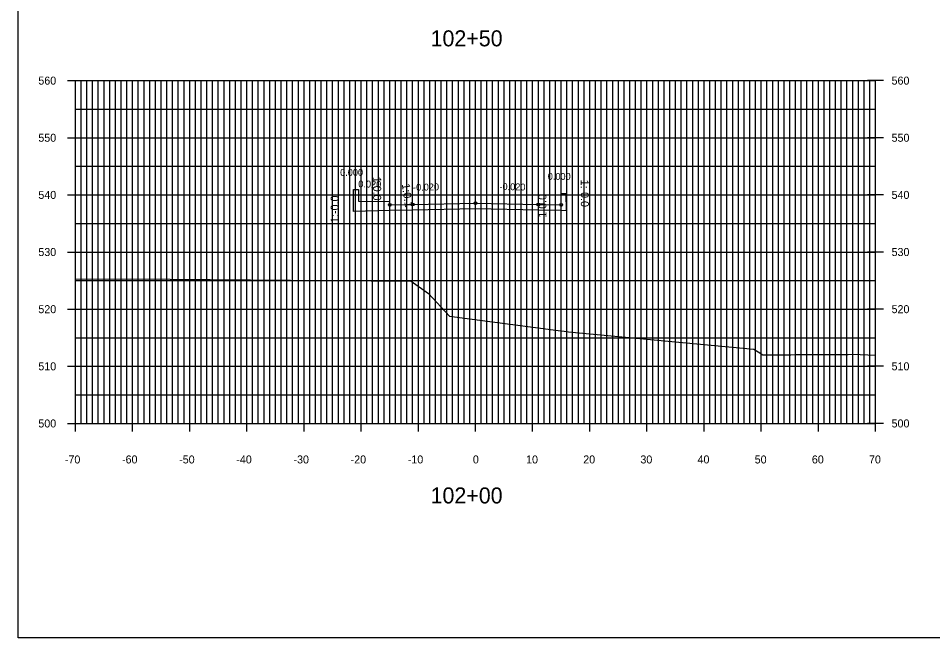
# Model space of a CAD drawing. Extents: x 1509063 to 1512863, y 401160 to 402918.
# Drawn here: x 1511462.7 to 1511622.7, y 402252.1 to 402360.5 of the extents above; entities that cross this region are included whole.
import ezdxf

# ---------------------------------------------------------------- set-up
doc = ezdxf.new("R2010")
doc.units = 0
for name, color, linetype in [('NBL1', 7, 'Continuous'), ('PET_P', 7, 'Continuous'), ('PRC', 7, 'Continuous'), ('PSP_P', 7, 'Continuous'), ('XAX_P', 7, 'Continuous'), ('XAXTIC_P', 7, 'Continuous'), ('XAXTXT_P_T', 7, 'Continuous'), ('XGL_P', 7, 'Continuous'), ('XSL1_P', 7, 'Continuous'), ('XSL1_P_T', 7, 'Continuous'), ('XSL3_P', 7, 'Continuous'), ('XSLOG', 7, 'Continuous')]:
    doc.layers.add(name, color=color, linetype=linetype)

msp = doc.modelspace()

# ---------------------------------------------------------------- linework, layer by layer
at = {"layer": 'NBL1'}
msp.add_lwpolyline([(1511782.73, 402252.08), (1511462.73, 402252.08), (1511462.73, 402462.08), (1511782.73, 402462.08)], close=True, dxfattribs=at)
at = {"layer": 'PET_P'}
for centre in [(1511531.73, 402327.9), (1511553.73, 402327.9)]:
    msp.add_circle(centre, 0.25, dxfattribs=at)
at = {"layer": 'PRC'}
msp.add_circle((1511542.73, 402328.12), 0.25, dxfattribs=at)
at = {"layer": 'PSP_P'}
for centre in [(1511527.73, 402327.82), (1511557.73, 402327.82)]:
    msp.add_circle(centre, 0.25, dxfattribs=at)
at = {"layer": 'XAX_P'}
for p, q in [((1511472.73, 402289.58), (1511472.73, 402349.58)), ((1511542.73, 402289.58), (1511542.73, 402349.58)), ((1511612.73, 402289.58), (1511612.73, 402349.58)), ((1511472.73, 402289.58), (1511612.73, 402289.58))]:
    msp.add_line(p, q, dxfattribs=at)
at = {"layer": 'XAXTIC_P'}
for p, q in [((1511471.33, 402349.58), (1511474.13, 402349.58)), ((1511541.33, 402349.58), (1511544.13, 402349.58)), ((1511614.13, 402349.58), (1511611.33, 402349.58)), ((1511471.33, 402339.58), (1511474.13, 402339.58)), ((1511541.33, 402339.58), (1511544.13, 402339.58)), ((1511614.13, 402339.58), (1511611.33, 402339.58)), ((1511471.33, 402329.58), (1511474.13, 402329.58)), ((1511541.33, 402329.58), (1511544.13, 402329.58)), ((1511614.13, 402329.58), (1511611.33, 402329.58)), ((1511471.33, 402319.58), (1511474.13, 402319.58)), ((1511541.33, 402319.58), (1511544.13, 402319.58)), ((1511614.13, 402319.58), (1511611.33, 402319.58)), ((1511471.33, 402309.58), (1511474.13, 402309.58)), ((1511541.33, 402309.58), (1511544.13, 402309.58)), ((1511614.13, 402309.58), (1511611.33, 402309.58)), ((1511471.33, 402299.58), (1511474.13, 402299.58)), ((1511541.33, 402299.58), (1511544.13, 402299.58)), ((1511614.13, 402299.58), (1511611.33, 402299.58)), ((1511472.73, 402288.18), (1511472.73, 402290.98)), ((1511482.73, 402288.18), (1511482.73, 402290.98)), ((1511492.73, 402288.18), (1511492.73, 402290.98)), ((1511502.73, 402288.18), (1511502.73, 402290.98)), ((1511512.73, 402288.18), (1511512.73, 402290.98)), ((1511522.73, 402288.18), (1511522.73, 402290.98)), ((1511532.73, 402288.18), (1511532.73, 402290.98)), ((1511542.73, 402288.18), (1511542.73, 402290.98)), ((1511552.73, 402288.18), (1511552.73, 402290.98)), ((1511562.73, 402288.18), (1511562.73, 402290.98)), ((1511572.73, 402288.18), (1511572.73, 402290.98)), ((1511582.73, 402288.18), (1511582.73, 402290.98)), ((1511592.73, 402288.18), (1511592.73, 402290.98)), ((1511602.73, 402288.18), (1511602.73, 402290.98)), ((1511612.73, 402288.18), (1511612.73, 402290.98)), ((1511471.33, 402289.58), (1511474.13, 402289.58)), ((1511541.33, 402289.58), (1511544.13, 402289.58)), ((1511614.13, 402289.58), (1511611.33, 402289.58))]:
    msp.add_line(p, q, dxfattribs=at)
at = {"layer": 'XGL_P'}
for p, q in [((1511472.73, 402349.58), (1511612.73, 402349.58)), ((1511472.73, 402289.58), (1511472.73, 402349.58)), ((1511473.73, 402289.58), (1511473.73, 402349.58)), ((1511474.73, 402289.58), (1511474.73, 402349.58)), ((1511475.73, 402289.58), (1511475.73, 402349.58)), ((1511476.73, 402289.58), (1511476.73, 402349.58)), ((1511477.73, 402289.58), (1511477.73, 402349.58)), ((1511478.73, 402289.58), (1511478.73, 402349.58)), ((1511479.73, 402289.58), (1511479.73, 402349.58)), ((1511480.73, 402289.58), (1511480.73, 402349.58)), ((1511481.73, 402289.58), (1511481.73, 402349.58)), ((1511482.73, 402289.58), (1511482.73, 402349.58)), ((1511483.73, 402289.58), (1511483.73, 402349.58)), ((1511484.73, 402289.58), (1511484.73, 402349.58)), ((1511485.73, 402289.58), (1511485.73, 402349.58)), ((1511486.73, 402289.58), (1511486.73, 402349.58)), ((1511487.73, 402289.58), (1511487.73, 402349.58)), ((1511488.73, 402289.58), (1511488.73, 402349.58)), ((1511489.73, 402289.58), (1511489.73, 402349.58)), ((1511490.73, 402289.58), (1511490.73, 402349.58)), ((1511491.73, 402289.58), (1511491.73, 402349.58)), ((1511492.73, 402289.58), (1511492.73, 402349.58)), ((1511493.73, 402289.58), (1511493.73, 402349.58)), ((1511494.73, 402289.58), (1511494.73, 402349.58)), ((1511495.73, 402289.58), (1511495.73, 402349.58)), ((1511496.73, 402289.58), (1511496.73, 402349.58)), ((1511497.73, 402289.58), (1511497.73, 402349.58)), ((1511498.73, 402289.58), (1511498.73, 402349.58)), ((1511499.73, 402289.58), (1511499.73, 402349.58)), ((1511500.73, 402289.58), (1511500.73, 402349.58)), ((1511501.73, 402289.58), (1511501.73, 402349.58)), ((1511502.73, 402289.58), (1511502.73, 402349.58)), ((1511503.73, 402289.58), (1511503.73, 402349.58)), ((1511504.73, 402289.58), (1511504.73, 402349.58)), ((1511505.73, 402289.58), (1511505.73, 402349.58)), ((1511506.73, 402289.58), (1511506.73, 402349.58)), ((1511507.73, 402289.58), (1511507.73, 402349.58)), ((1511508.73, 402289.58), (1511508.73, 402349.58)), ((1511509.73, 402289.58), (1511509.73, 402349.58)), ((1511510.73, 402289.58), (1511510.73, 402349.58)), ((1511511.73, 402289.58), (1511511.73, 402349.58)), ((1511512.73, 402289.58), (1511512.73, 402349.58)), ((1511513.73, 402289.58), (1511513.73, 402349.58)), ((1511514.73, 402289.58), (1511514.73, 402349.58)), ((1511515.73, 402289.58), (1511515.73, 402349.58)), ((1511516.73, 402289.58), (1511516.73, 402349.58)), ((1511517.73, 402289.58), (1511517.73, 402349.58)), ((1511518.73, 402289.58), (1511518.73, 402349.58)), ((1511519.73, 402289.58), (1511519.73, 402349.58)), ((1511520.73, 402289.58), (1511520.73, 402349.58)), ((1511521.73, 402289.58), (1511521.73, 402349.58)), ((1511522.73, 402289.58), (1511522.73, 402349.58)), ((1511523.73, 402289.58), (1511523.73, 402349.58)), ((1511524.73, 402289.58), (1511524.73, 402349.58)), ((1511525.73, 402289.58), (1511525.73, 402349.58)), ((1511526.73, 402289.58), (1511526.73, 402349.58)), ((1511527.73, 402289.58), (1511527.73, 402349.58)), ((1511528.73, 402289.58), (1511528.73, 402349.58)), ((1511529.73, 402289.58), (1511529.73, 402349.58)), ((1511530.73, 402289.58), (1511530.73, 402349.58)), ((1511531.73, 402289.58), (1511531.73, 402349.58)), ((1511532.73, 402289.58), (1511532.73, 402349.58)), ((1511533.73, 402289.58), (1511533.73, 402349.58)), ((1511534.73, 402289.58), (1511534.73, 402349.58)), ((1511535.73, 402289.58), (1511535.73, 402349.58)), ((1511536.73, 402289.58), (1511536.73, 402349.58)), ((1511537.73, 402289.58), (1511537.73, 402349.58)), ((1511538.73, 402289.58), (1511538.73, 402349.58)), ((1511539.73, 402289.58), (1511539.73, 402349.58)), ((1511540.73, 402289.58), (1511540.73, 402349.58)), ((1511541.73, 402289.58), (1511541.73, 402349.58)), ((1511542.73, 402289.58), (1511542.73, 402349.58)), ((1511543.73, 402289.58), (1511543.73, 402349.58)), ((1511544.73, 402289.58), (1511544.73, 402349.58)), ((1511545.73, 402289.58), (1511545.73, 402349.58)), ((1511546.73, 402289.58), (1511546.73, 402349.58)), ((1511547.73, 402289.58), (1511547.73, 402349.58)), ((1511548.73, 402289.58), (1511548.73, 402349.58)), ((1511549.73, 402289.58), (1511549.73, 402349.58)), ((1511550.73, 402289.58), (1511550.73, 402349.58)), ((1511551.73, 402289.58), (1511551.73, 402349.58)), ((1511552.73, 402289.58), (1511552.73, 402349.58)), ((1511553.73, 402289.58), (1511553.73, 402349.58)), ((1511554.73, 402289.58), (1511554.73, 402349.58)), ((1511555.73, 402289.58), (1511555.73, 402349.58)), ((1511556.73, 402289.58), (1511556.73, 402349.58)), ((1511557.73, 402289.58), (1511557.73, 402349.58)), ((1511558.73, 402289.58), (1511558.73, 402349.58)), ((1511559.73, 402289.58), (1511559.73, 402349.58)), ((1511560.73, 402289.58), (1511560.73, 402349.58)), ((1511561.73, 402289.58), (1511561.73, 402349.58)), ((1511562.73, 402289.58), (1511562.73, 402349.58)), ((1511563.73, 402289.58), (1511563.73, 402349.58)), ((1511564.73, 402289.58), (1511564.73, 402349.58)), ((1511565.73, 402289.58), (1511565.73, 402349.58)), ((1511566.73, 402289.58), (1511566.73, 402349.58)), ((1511567.73, 402289.58), (1511567.73, 402349.58)), ((1511568.73, 402289.58), (1511568.73, 402349.58)), ((1511569.73, 402289.58), (1511569.73, 402349.58)), ((1511570.73, 402289.58), (1511570.73, 402349.58)), ((1511571.73, 402289.58), (1511571.73, 402349.58)), ((1511572.73, 402289.58), (1511572.73, 402349.58)), ((1511573.73, 402289.58), (1511573.73, 402349.58)), ((1511574.73, 402289.58), (1511574.73, 402349.58)), ((1511575.73, 402289.58), (1511575.73, 402349.58)), ((1511576.73, 402289.58), (1511576.73, 402349.58)), ((1511577.73, 402289.58), (1511577.73, 402349.58)), ((1511578.73, 402289.58), (1511578.73, 402349.58)), ((1511579.73, 402289.58), (1511579.73, 402349.58)), ((1511580.73, 402289.58), (1511580.73, 402349.58)), ((1511581.73, 402289.58), (1511581.73, 402349.58)), ((1511582.73, 402289.58), (1511582.73, 402349.58)), ((1511583.73, 402289.58), (1511583.73, 402349.58)), ((1511584.73, 402289.58), (1511584.73, 402349.58)), ((1511585.73, 402289.58), (1511585.73, 402349.58)), ((1511586.73, 402289.58), (1511586.73, 402349.58)), ((1511587.73, 402289.58), (1511587.73, 402349.58)), ((1511588.73, 402289.58), (1511588.73, 402349.58)), ((1511589.73, 402289.58), (1511589.73, 402349.58)), ((1511590.73, 402289.58), (1511590.73, 402349.58)), ((1511591.73, 402289.58), (1511591.73, 402349.58)), ((1511592.73, 402289.58), (1511592.73, 402349.58)), ((1511593.73, 402289.58), (1511593.73, 402349.58)), ((1511594.73, 402289.58), (1511594.73, 402349.58)), ((1511595.73, 402289.58), (1511595.73, 402349.58)), ((1511596.73, 402289.58), (1511596.73, 402349.58)), ((1511597.73, 402289.58), (1511597.73, 402349.58)), ((1511598.73, 402289.58), (1511598.73, 402349.58)), ((1511599.73, 402289.58), (1511599.73, 402349.58)), ((1511600.73, 402289.58), (1511600.73, 402349.58)), ((1511601.73, 402289.58), (1511601.73, 402349.58)), ((1511602.73, 402289.58), (1511602.73, 402349.58)), ((1511603.73, 402289.58), (1511603.73, 402349.58)), ((1511604.73, 402289.58), (1511604.73, 402349.58)), ((1511605.73, 402289.58), (1511605.73, 402349.58)), ((1511606.73, 402289.58), (1511606.73, 402349.58)), ((1511607.73, 402289.58), (1511607.73, 402349.58)), ((1511608.73, 402289.58), (1511608.73, 402349.58)), ((1511609.73, 402289.58), (1511609.73, 402349.58)), ((1511610.73, 402289.58), (1511610.73, 402349.58)), ((1511611.73, 402289.58), (1511611.73, 402349.58)), ((1511612.73, 402289.58), (1511612.73, 402349.58)), ((1511472.73, 402344.58), (1511612.73, 402344.58)), ((1511472.73, 402339.58), (1511612.73, 402339.58)), ((1511472.73, 402334.58), (1511612.73, 402334.58)), ((1511472.73, 402329.58), (1511612.73, 402329.58)), ((1511472.73, 402324.58), (1511612.73, 402324.58)), ((1511472.73, 402319.58), (1511612.73, 402319.58)), ((1511472.73, 402314.58), (1511612.73, 402314.58)), ((1511472.73, 402309.58), (1511612.73, 402309.58)), ((1511472.73, 402304.58), (1511612.73, 402304.58)), ((1511472.73, 402299.58), (1511612.73, 402299.58)), ((1511472.73, 402294.58), (1511612.73, 402294.58)), ((1511472.73, 402289.58), (1511612.73, 402289.58))]:
    msp.add_line(p, q, dxfattribs=at)
at = {"layer": 'XSL1_P'}
msp.add_lwpolyline([(1511521.39, 402326.69), (1511521.4, 402330.51), (1511522.23, 402330.51), (1511522.23, 402328.51), (1511527.65, 402328.4), (1511527.73, 402327.82), (1511531.73, 402327.9), (1511542.73, 402328.12), (1511553.73, 402327.9), (1511557.73, 402327.82), (1511557.73, 402329.82), (1511558.56, 402329.82), (1511558.57, 402326.8)], dxfattribs=at)
at = {"layer": 'XSL3_P'}
msp.add_lwpolyline([(1511531.73, 402326.9), (1511527.73, 402326.82), (1511521.39, 402326.69), (1511521.4, 402330.51), (1511522.23, 402330.51), (1511522.23, 402328.51), (1511527.65, 402328.4), (1511527.73, 402327.82), (1511531.73, 402327.9), (1511542.72, 402328.12), (1511553.73, 402327.9), (1511557.73, 402327.82), (1511557.73, 402329.82), (1511558.56, 402329.82), (1511558.57, 402326.8), (1511557.73, 402326.82), (1511553.73, 402326.9), (1511542.72, 402327.12)], close=True, dxfattribs=at)
at = {"layer": 'XSLOG'}
msp.add_lwpolyline([(1511472.73, 402314.91), (1511489.32, 402314.84), (1511531.48, 402314.48), (1511534.5, 402312.32), (1511538.18, 402308.35), (1511557.18, 402305.86), (1511558.27, 402305.72), (1511559, 402305.59), (1511591.44, 402302.59), (1511592.19, 402302.11), (1511593.01, 402301.58), (1511593.7, 402301.59), (1511594.39, 402301.59), (1511595.08, 402301.6), (1511595.78, 402301.6), (1511596.48, 402301.6), (1511597.18, 402301.61), (1511597.88, 402301.61), (1511598.58, 402301.62), (1511599.29, 402301.62), (1511600, 402301.63), (1511600.71, 402301.63), (1511601.42, 402301.63), (1511602.14, 402301.64), (1511602.86, 402301.64), (1511603.57, 402301.65), (1511604.3, 402301.65), (1511605.02, 402301.65), (1511605.75, 402301.66), (1511606.48, 402301.66), (1511607.21, 402301.67), (1511607.94, 402301.67), (1511608.68, 402301.68), (1511612.73, 402301.54)], dxfattribs=at)

# ---------------------------------------------------------------- texts
at = {"layer": 'XAXTXT_P_T'}
for s, height, p in [('102+50', 2.8, (1511534.87, 402355.58)), ('560', 1.4, (1511466.24, 402348.88)), ('560', 1.4, (1511615.53, 402348.88)), ('550', 1.4, (1511466.24, 402338.88)), ('550', 1.4, (1511615.53, 402338.88)), ('540', 1.4, (1511466.24, 402328.88)), ('540', 1.4, (1511615.53, 402328.88)), ('530', 1.4, (1511466.24, 402318.88)), ('530', 1.4, (1511615.53, 402318.88)), ('520', 1.4, (1511466.24, 402308.88)), ('520', 1.4, (1511615.53, 402308.88)), ('510', 1.4, (1511466.24, 402298.88)), ('510', 1.4, (1511615.53, 402298.88)), ('500', 1.4, (1511466.24, 402288.88)), ('500', 1.4, (1511615.53, 402288.88)), ('-70', 1.4, (1511470.88, 402282.58)), ('-60', 1.4, (1511480.88, 402282.58)), ('-50', 1.4, (1511490.88, 402282.58)), ('-40', 1.4, (1511500.88, 402282.58)), ('-30', 1.4, (1511510.88, 402282.58)), ('-20', 1.4, (1511520.88, 402282.58)), ('-10', 1.4, (1511530.88, 402282.58)), ('0', 1.4, (1511542.27, 402282.58)), ('10', 1.4, (1511551.58, 402282.58)), ('20', 1.4, (1511561.58, 402282.58)), ('30', 1.4, (1511571.58, 402282.58)), ('40', 1.4, (1511581.58, 402282.58)), ('50', 1.4, (1511591.58, 402282.58)), ('60', 1.4, (1511601.58, 402282.58)), ('70', 1.4, (1511611.58, 402282.58)), ('102+00', 2.8, (1511534.87, 402275.58))]:
    msp.add_text(s, height=height, dxfattribs=at).set_placement(p)
at = {"layer": 'XSL1_P_T'}
for s, height, rotation, p in [('0.000', 1.2, 360, (1511519.04, 402332.91)), ('0.000', 1.2, 360, (1511519.04, 402332.91)), ('0.000', 1.2, 360, (1511555.37, 402332.22)), ('0.000', 1.2, 360, (1511555.37, 402332.22)), ('0.020', 1.2, 358.8542, (1511522.21, 402330.91)), ('0.020', 1.2, 358.8542, (1511522.21, 402330.91)), ('1:0.0', 1.4, 270.0286, (1511524.83, 402332.75)), ('1:0.0', 1.4, 270.0286, (1511524.83, 402332.75)), ('1:0.1', 1.4, 278.1301, (1511529.83, 402331.46)), ('1:0.1', 1.4, 278.1301, (1511529.83, 402331.46)), ('-0.020', 1.2, 1.1458, (1511531.81, 402330.3)), ('-0.020', 1.2, 1.1458, (1511531.81, 402330.3)), ('-0.020', 1.2, 1.1458, (1511531.81, 402330.3)), ('-0.020', 1.2, 358.8542, (1511546.91, 402330.44)), ('-0.020', 1.2, 358.8542, (1511546.91, 402330.44)), ('-0.020', 1.2, 358.8542, (1511546.91, 402330.44)), ('1:-0.0', 1.4, 270.1899, (1511561.15, 402332.25)), ('1:-0.0', 1.4, 270.1899, (1511561.15, 402332.25)), ('1:0.0', 1.4, 89.9714, (1511555.13, 402325.58)), ('1:0.0', 1.4, 89.9714, (1511555.13, 402325.58)), ('1:-0.0', 1.4, 89.85, (1511518.78, 402324.68)), ('1:-0.0', 1.4, 89.85, (1511518.78, 402324.68))]:
    msp.add_text(s, height=height, rotation=rotation, dxfattribs=at).set_placement(p)

doc.saveas('drawing.dxf')
